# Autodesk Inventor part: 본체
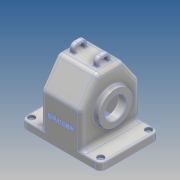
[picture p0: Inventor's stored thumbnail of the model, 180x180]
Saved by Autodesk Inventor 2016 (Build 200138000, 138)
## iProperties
Created: 2016-12
Part Number: 본체
Material: 알루미늄 6061
Document SubType Name: Modeling
Designer: Administrator
Density: 2.7 g/cm^3
Appearance: 알루미늄 - 평지
Mass: 1051.15 g
Surface Area: 1136.66 cm^2
Volume: 389.314 cm^3
Author: Administrator
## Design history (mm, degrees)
sketch "스케치1"
  geometry: L1 (-75, 55)-(75, 55); L2 (75, 55)-(75, -55); L3 (75, -55)-(-75, -55); L4 (-75, -55)-(-75, 55); L5 (-75, 55)-(75, -55); L6 (75, 55)-(-75, -55); 1 further point
  constraints: 12 end point, 2 midpoint, 2 parallel, 1 horizontal, 1 perpendicular
  dimensions: "d0" = 150 distance of L2.end L3.end; "d1" = 110 distance of L1.end L2.end
extrude "돌출1" new body sketch "스케치1" distance "d2" = 15; taper "d3" = 0 deg
fillet "모깎기1" dims "d4" = 10
sketch "스케치2"
  geometry: A1 r 10 centre (65, -45) between (65, -55) and (75, -45) reference; A2 r 10 centre (65, 45) between (75, 45) and (65, 55) reference; A3 r 10 centre (-65, 45) between (-65, 55) and (-75, 45) reference; A4 r 10 centre (-65, -45) between (-75, -45) and (-65, -55) reference; 5 further points
  constraints: 4 coincident
hole "구멍1" sketch "스케치2" at (-65, 45), (-65, -45), (65, -45), (65, 45) diameter "d5" = 5; stored, may be unused: countersink angle "d9" = 90 deg, drill point angle "d11" = 118 deg; dims "d6" = 6, "d7" = 12, "d8" = 5, "d10" = 8
sketch "스케치3"
  geometry: L1 (-65, 15)-(65, 15) reference; L2 (38.5, 15)-(38.5, 125); L3 (38.5, 125)-(-38.5, 125); L4 (-38.5, 125)-(-38.5, 15); L5 (65, 0)-(-65, 0) reference; 3 further points
  constraints: 6 end point, 2 midpoint, 2 point on line, 2 vertical, 1 horizontal, 1 vertical alignment
  dimensions: "d12" = 77 distance between parallel lines of L4 L2; "d13" = 125 distance between parallel lines of L5 L3
extrude "돌출2" join sketch "스케치3" stored distance "d14" = 110; taper "d15" = 0 deg
sketch "스케치4"
  geometry: L1 (-110, 110)-(0, 110) reference; L2 (-110, 0)-(-110, 110) reference; L3 (0, 0)-(-110, 0) reference; L4 (-65, 0)-(-110, 31.509); L5 (-110, 78.491)-(-65, 110); L6 (15, 110)-(15, 100) reference; L7 (15, 100)-(15, 10) reference; 1 further point
  constraints: 4 end point, 4 point on line, 1 equal length
  dimensions: "d16" = 80 distance from line of L6 L5.end; "d17" = 80 distance from line of L7 L4.start; "d18" = 35 deg angle of L4 L3
extrude "돌출3" cut sketch "스케치4" stored distance "d19" = 110; taper "d20" = 0 deg
node "작업 평면1"
sketch "스케치5"
  geometry: L1 (-15, 10)-(0, 10) reference; L2 (-15, 100)-(-15, 10) reference; L3 (0, 100)-(-15, 100) reference; L4 (0, 10)-(0, 100) reference; L5 (-15, 100)-(-15, 10) reference; C1 r 31 at (50, 55); 2 further points
  constraints: 1 centre point, 1 horizontal alignment, 1 midpoint
  dimensions: "d22" = 62 diameter of C1; "d23" = 65 distance from line of L2 C1.centre
extrude "돌출4" join sketch "스케치5" stored distance "d24" = 0; taper "d25" = 0 deg
node "작업 평면2"
sketch "스케치6"
  geometry: L1 (-15, 10)-(-15, 100) reference; C1 r 37.5 at (50, 55); 2 further points
  constraints: 1 centre point, 1 horizontal alignment, 1 midpoint
  dimensions: "d27" = 75 diameter of C1; "d28" = 65 distance from line of L1 C1.centre
extrude "돌출5" join sketch "스케치6" stored distance "d29" = 110; taper "d30" = 0 deg
sketch "스케치10"
  geometry: L1 (50, 0)-(50, 78.424); L2 (50, 78.424)-(20.888, 120); L3 (20.888, 120)-(-20.888, 120); L4 (-20.888, 120)-(-50, 78.424); L5 (-50, 78.424)-(-50, 0); L6 (45, 0)-(-45, 0) reference; L7 (-55, 15)-(-55, 80) reference; L8 (-23.491, 125)-(-55, 80) reference; L9 (-23.491, 125)-(23.491, 125) reference; L10 (55, 80)-(23.491, 125) reference; L11 (55, 80)-(55, 15) reference; L12 (50, 0)-(-50, 0); 1 further point
  constraints: 12 end point, 2 horizontal, 2 parallel, 2 point on line, 2 vertical, 1 horizontal alignment
  dimensions: "d43" = 5 distance between parallel lines of L5 L7; "d44" = 5 distance between parallel lines of L1 L11; "d45" = 5 distance between parallel lines of L3 L9; "d48" = 5 distance between parallel lines of L8 L4
extrude "돌출6" cut sketch "스케치10" stored distance "d49" = 67; taper "d50" = 0 deg
sketch "스케치11"
  geometry: L1 (43.5, 65)-(-86.441, 65); L2 (33.5, 120)-(33.5, 78.424) reference; L3 (33.5, 106)-(19.5, 92); L4 (19.5, 92)-(19.5, 65); L5 (33.5, 106)-(33.5, 65); L6 (43.5, 102.5)-(43.5, 27.5) reference; 1 further point
  constraints: 8 end point, 3 point on line, 1 horizontal, 1 perpendicular, 1 vertical
  dimensions: "d53" = 54 diameter of L3.end L1; "d54" = 45 deg angle of L4 L3; "d98" = 24 distance between parallel lines of L6 L4; "d100" = 65 vertical distance of point (0, 0) L4.end
revolve "회전1" sketch "스케치11" stored, may be unused: angle "d56" = 90 deg
hole "구멍3" diameter "d59" = 40; stored, may be unused: countersink angle "d63" = 90 deg, drill point angle "d65" = 118 deg; dims "d57" = 10, "d58" = 10, "d60" = 6, "d61" = 12, "d62" = 5, "d64" = 8
sketch "스케치12"
  geometry: C1 r 20 at (0, 0) reference; 5 further points
  constraints: 2 horizontal alignment, 2 vertical alignment
  dimensions: "d66" = 52 distance of point (26, 0) point (-26, 0); "d67" = 26 distance of point (-26, 0) C1.centre; "d68" = 52 distance of point (0, -26) point (0, 26); "d69" = 26 distance of point (0, -26) C1.centre
hole "구멍4" sketch "스케치12" at (-26, 0), (0, -26), (0, 26), (26, 0) diameter "d70" = 2.459; stored, may be unused: countersink angle "d74" = 90 deg, drill point angle "d76" = 118 deg; dims "d71" = 6, "d72" = 12, "d73" = 5, "d75" = 8
sketch "스케치13"
  geometry: C1 r 20 at (0, 0) reference; 5 further points
  constraints: 2 horizontal alignment, 2 vertical alignment
  dimensions: "d77" = 58 distance of point (-29, 0) point (29, 0); "d78" = 58 distance of point (0, -29) point (0, 29); "d79" = 29 distance of C1.centre point (29, 0); "d80" = 29 distance of point (0, -29) C1.centre
hole "구멍5" sketch "스케치13" at (29, 0), (0, 29), (-29, 0), (0, -29) diameter "d81" = 2.459; stored, may be unused: countersink angle "d85" = 90 deg, drill point angle "d87" = 118 deg; dims "d82" = 6, "d83" = 12, "d84" = 5, "d86" = 8
node "작업 평면3"
sketch "스케치14"
  geometry: L1 (55, 80)-(23.491, 125) reference; L2 (-23.491, 125)-(23.491, 125) reference; L3 (-23.491, 125)-(-55, 80) reference; L4 (-55, 15)-(-55, 80) reference; L5 (55, 15)-(-55, 15) reference; L6 (55, 80)-(55, 15) reference; L7 (-23.491, 125)-(23.491, 125) reference; L8 (-12.5, 125)-(-12.5, 140); L9 (-12.5, 140)-(12.5, 140); L10 (12.5, 140)-(12.5, 125); L11 (-7.5, 125)-(-7.5, 135); L12 (-7.5, 135)-(7.5, 135); L13 (7.5, 135)-(7.5, 125); L14 (45, 0)-(-45, 0) reference; C1 r 31 at (0, 65) reference; 3 further points
  constraints: 12 end point, 4 point on line, 3 perpendicular, 3 vertical, 2 midpoint, 2 vertical alignment
  dimensions: "d89" = 25 distance between parallel lines of L8 L10; "d90" = 15 distance between parallel lines of L11 L13; "d91" = 140 distance between parallel lines of L14 L9; "d92" = 5 distance between parallel lines of L12 L9
extrude "돌출7" join sketch "스케치14" distance "d93" = 8; taper "d94" = 0 deg
fillet "모깎기3" dims "d96" = 1
fillet "모깎기4" dims "d97" = 8
fillet "모깎기5" dims "d101" = 1, "d113" = 3
fillet "모깎기6" dims "d102" = 3
fillet "모깎기7" dims "d103" = 3
node "작업 평면5"
sketch "스케치15"
  geometry: L1 (-38.5, 12)-(-38.5, 80) reference; 3 further points
  constraints: 1 other
  dimensions: "d105" = 45 distance of point (0, 0) point (0, 45); "d117" = 38.5 distance from line of point (0, 45) L1
feature "엠보싱1" sketch "스케치15" dims "d0" = 150, "d1" = 110, "d107" = 0.5, "d108" = 0
chamfer "모따기1" distance "d109" = 1; stored, may be unused: second distance "d110" = 2, angle "d111" = 45 deg
fillet "모깎기9" dims "d114" = 3
fillet "모깎기10" dims "d115" = 10
fillet "모깎기11" dims "d116" = 8
fillet "모깎기12" dims "d118" = 8
node "솔리드1"
mirror "대칭1"
node "투영된 루프1"
node "투영된 루프2"
node "작업 평면4"
other parameters: "d21" = -87, "d26" = 5, "d88" = 26
